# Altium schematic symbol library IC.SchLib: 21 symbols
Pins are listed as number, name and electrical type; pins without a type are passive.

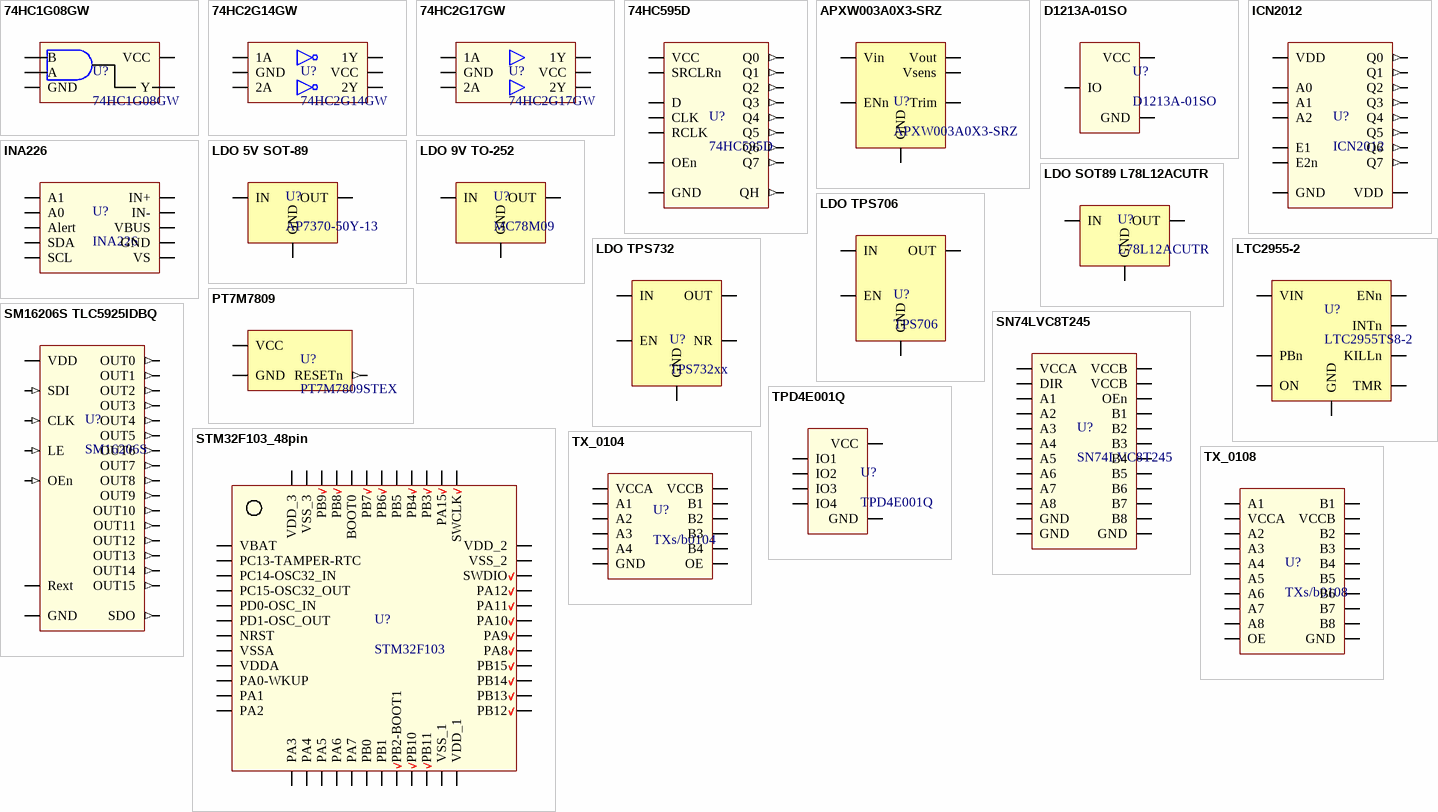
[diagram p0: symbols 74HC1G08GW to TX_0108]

## 74HC1G08GW
designator U?
footprint TSSOP5_SOT353-NXP
pins: 1 B, 2 A, 3 GND, 4 Y, 5 VCC

## 74HC2G14GW
designator U?
footprint TSSOP6_SOT363-NXP
pins: 1 1A, 2 GND, 3 2A, 4 2Y, 5 VCC, 6 1Y

## 74HC2G17GW
designator U?
footprint TSSOP6_SOT363-NXP
pins: 1 1A, 2 GND, 3 2A, 4 2Y, 5 VCC, 6 1Y

## 74HC595D
designator U?
footprint SOP-16-TI
pins: 1 Q1 (out), 2 Q2 (out), 3 Q3 (out), 4 Q4 (out), 5 Q5 (out), 6 Q6 (out), 7 Q7 (out), 8 GND, 9 QH (out), 10 SRCLRn, 11 CLK, 12 RCLK, 13 OEn, 14 D, 15 Q0 (out), 16 VCC

## APXW003A0X3-SRZ
designator U?
footprint DC-DC ProLynx
pins: ENn, GND, Trim, Vin, Vout, Vsens

## D1213A-01SO
designator U?
pins: 1 IO, 2 VCC, 3 GND

## ICN2012
designator U?
footprint SOP-16-TI
pins: 1 VDD, 2 A2, 3 Q0 (out), 4 Q1 (out), 5 Q2 (out), 6 Q3 (out), 7 E1, 8 GND, 9 VDD, 10 E2n, 11 Q4 (out), 12 Q5 (out), 13 Q6 (out), 14 Q7 (out), 15 A0, 16 A1

## INA226
designator U?
footprint VSSOP10-TI
pins: 1 A1, 2 A0, 3 Alert, 4 SDA, 5 SCL, 6 VS, 7 GND, 8 VBUS, 9 IN-, 10 IN+

## LDO 5V SOT-89
designator U?, comment AP7370-50Y-13
footprint SOT-89; pin to pad GND>2 IN>3 OUT>1
pins: GND, IN, OUT

## LDO 9V TO-252
designator U?, comment MC78M09
footprint TO-252-3; pin to pad GND>2 IN>1 OUT>3
pins: GND, IN, OUT

## LDO SOT89 L78L12ACUTR
designator U?, comment L78L12ACUTR
footprint SOT-89; pin to pad GND>2 IN>3 OUT>1
pins: GND, IN, OUT

## LDO TPS706
designator U?, comment TPS706
footprint SOT-23-5-TI; pin to pad EN>3 GND>2 IN>1 OUT>5
pins: EN, GND, IN, OUT

## LDO TPS732
designator U?, comment TPS732xx
footprint SOT-223-6; pin to pad EN>5 GND>3+6 IN>1 NR>4 OUT>2
pins: EN, GND, IN, NR, OUT

## LTC2955-2
designator U?, comment LTC2955TS8-2
footprint TSOT-23-8-LTC
pins: 1 ON, 2 KILLn, 3 TMR, 4 GND, 5 PBn, 6 VIN, 7 ENn, 8 INTn

## PT7M7809
designator U?, comment PT7M7809STEX
footprint SOT23
pins: 1 GND, 2 RESETn (out), 3 VCC

## SM16206S TLC5925IDBQ
designator U?, comment SM16206S
footprint QSOP-24-ON
pins: 1 GND (power), 2 SDI (in), 3 CLK (in), 4 LE (in), 5 OUT0 (out), 6 OUT1 (out), 7 OUT2 (out), 8 OUT3 (out), 9 OUT4 (out), 10 OUT5 (out), 11 OUT6 (out), 12 OUT7 (out), 13 OUT8 (out), 14 OUT9 (out), 15 OUT10 (out), 16 OUT11 (out), 17 OUT12 (out), 18 OUT13 (out), 19 OUT14 (out), 20 OUT15 (out), 21 OEn (in), 22 SDO (out), 23 Rext, 24 VDD (power)

## SN74LVC8T245
designator U?
footprint TSSOP24-TI
pins: 1 VCCA, 2 DIR, 3 A1, 4 A2, 5 A3, 6 A4, 7 A5, 8 A6, 9 A7, 10 A8, 11 GND, 12 GND, 13 GND, 14 B8, 15 B7, 16 B6, 17 B5, 18 B4, 19 B3, 20 B2, 21 B1, 22 OEn, 23 VCCB, 24 VCCB

## STM32F103_48pin
designator U?, comment STM32F103
footprint QFP48
pins: 1 VBAT, 2 PC13-TAMPER-RTC, 3 PC14-OSC32_IN, 4 PC15-OSC32_OUT, 5 PD0-OSC_IN, 6 PD1-OSC_OUT, 7 NRST, 8 VSSA, 9 VDDA, 10 PA0-WKUP, 11 PA1, 12 PA2, 13 PA3, 14 PA4, 15 PA5, 16 PA6, 17 PA7, 18 PB0, 19 PB1, 20 PB2-BOOT1, 21 PB10, 22 PB11, 23 VSS_1, 24 VDD_1, 25 PB12, 26 PB13, 27 PB14, 28 PB15, 29 PA8, 30 PA9, 31 PA10, 32 PA11, 33 PA12, 34 SWDIO, 35 VSS_2, 36 VDD_2, 37 SWCLK, 38 PA15, 39 PB3, 40 PB4, 41 PB5, 42 PB6, 43 PB7, 44 BOOT0, 45 PB8, 46 PB9, 47 VSS_3, 48 VDD_3

## TPD4E001Q
designator U?
footprint SOT-23-6
pins: 1 IO1, 2 GND, 3 IO2, 4 IO3, 5 VCC, 6 IO4

## TX_0104
designator U?, comment TXs/b0104
footprint TSSOP14-TI
pins: 1 VCCA, 2 A1, 3 A2, 4 A3, 5 A4, 7 GND, 8 OE, 10 B4, 11 B3, 12 B2, 13 B1, 14 VCCB

## TX_0108
designator U?, comment TXs/b0108
footprint TSSOP20-TI
pins: 1 A1, 2 VCCA, 3 A2, 4 A3, 5 A4, 6 A5, 7 A6, 8 A7, 9 A8, 10 OE, 11 GND, 12 B8, 13 B7, 14 B6, 15 B5, 16 B4, 17 B3, 18 B2, 19 VCCB, 20 B1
